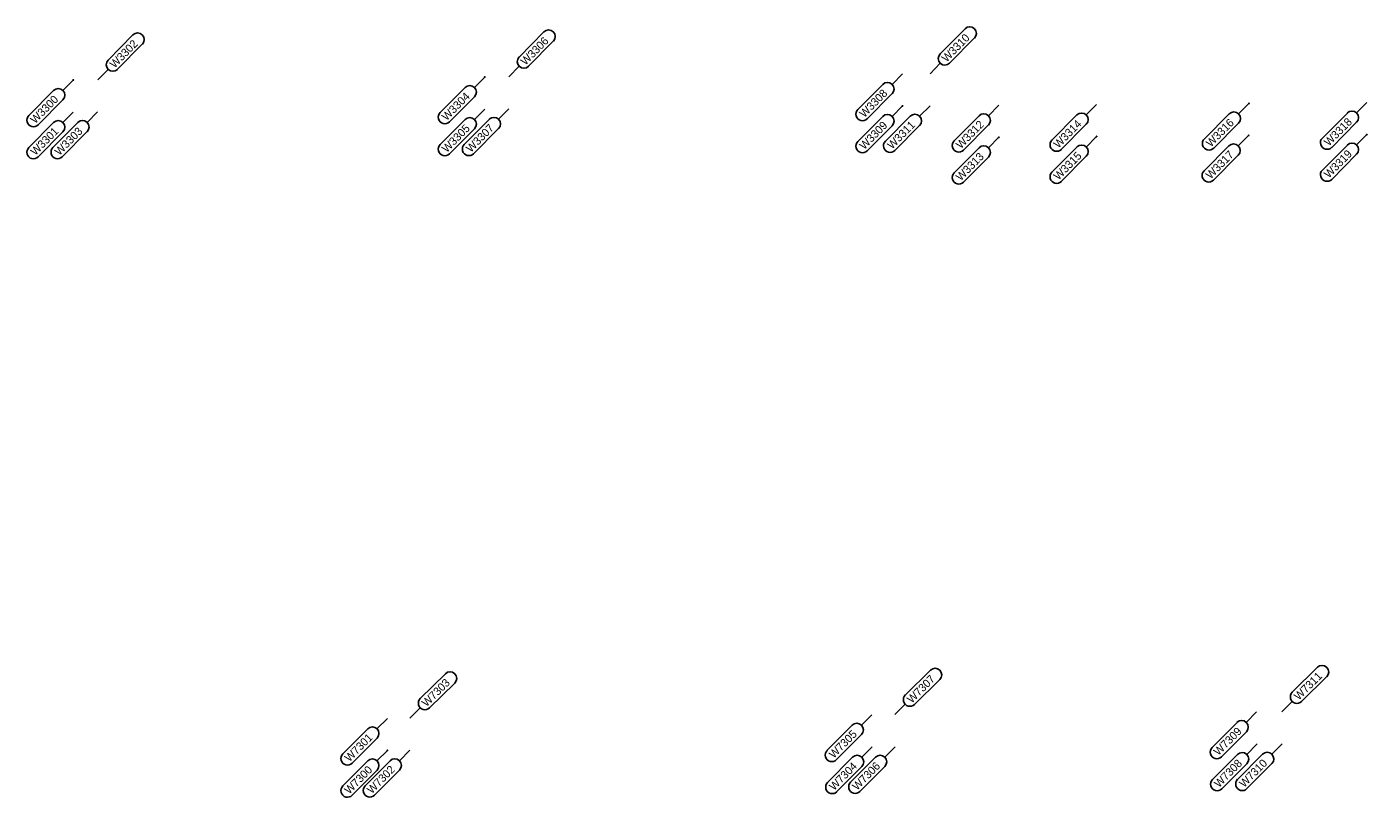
# Model space of a CAD drawing. Extents: x 12479652 to 12487250, y 9842710 to 9846560.
# Drawn here: x 12485622 to 12485831.3, y 9842757.5 to 9842877.8 of the extents above; entities that cross this region are included whole.
import ezdxf

# ---------------------------------------------------------------- set-up
doc = ezdxf.new("R2010")
doc.units = 0
doc.layers.add('_CIVIL_CONSTRUCTION', color=7, linetype='Continuous')
doc.layers.add('TextAlignmentLrg', color=7, linetype='Continuous')

msp = doc.modelspace()

# ---------------------------------------------------------------- linework, layer by layer
at = {"layer": '_CIVIL_CONSTRUCTION'}
for p, q in [((12485702.78, 9842876.99), (12485698.91, 9842873.07)), ((12485768.54, 9842877.48), (12485764.66, 9842873.55)), ((12485638.6, 9842876.52), (12485634.72, 9842872.59)), ((12485636.18, 9842871.15), (12485640.06, 9842875.08)), ((12485700.37, 9842871.62), (12485704.24, 9842875.55)), ((12485766.12, 9842872.11), (12485770, 9842876.04)), ((12485633.12, 9842869.5), (12485634.73, 9842871.14)), ((12485697.3, 9842869.98), (12485698.92, 9842871.62)), ((12485763.06, 9842870.46), (12485764.67, 9842872.1)), ((12485629.28, 9842869.48), (12485627.66, 9842867.84)), ((12485693.54, 9842869.95), (12485691.92, 9842868.32)), ((12485751.79, 9842864.88), (12485755.68, 9842868.8)), ((12485758.76, 9842870.43), (12485757.13, 9842868.8)), ((12485622.32, 9842863.93), (12485626.21, 9842867.84)), ((12485686.58, 9842864.4), (12485690.47, 9842868.31)), ((12485691.93, 9842866.87), (12485688.04, 9842862.96)), ((12485757.14, 9842867.35), (12485753.25, 9842863.44)), ((12485627.66, 9842866.39), (12485623.77, 9842862.48)), ((12485629.28, 9842864.48), (12485627.66, 9842862.84)), ((12485633.07, 9842864.5), (12485631.45, 9842862.87)), ((12485693.54, 9842864.95), (12485691.92, 9842863.32)), ((12485697.3, 9842864.98), (12485695.68, 9842863.35)), ((12485758.76, 9842865.43), (12485757.13, 9842863.8)), ((12485763.06, 9842865.46), (12485761.43, 9842863.83)), ((12485773.8, 9842865.54), (12485772.18, 9842863.91)), ((12485789.07, 9842865.66), (12485787.45, 9842864.02)), ((12485812.87, 9842865.83), (12485811.25, 9842864.2)), ((12485831.3, 9842865.97), (12485829.68, 9842864.34)), ((12485622.32, 9842858.93), (12485626.21, 9842862.84)), ((12485626.11, 9842858.95), (12485630, 9842862.87)), ((12485686.58, 9842859.4), (12485690.47, 9842863.31)), ((12485690.34, 9842859.43), (12485694.23, 9842863.34)), ((12485751.79, 9842859.88), (12485755.68, 9842863.8)), ((12485757.14, 9842862.35), (12485753.25, 9842858.44)), ((12485756.09, 9842859.92), (12485759.98, 9842863.83)), ((12485761.44, 9842862.38), (12485757.55, 9842858.47)), ((12485766.84, 9842859.99), (12485770.73, 9842863.91)), ((12485772.19, 9842862.46), (12485768.3, 9842858.55)), ((12485782.11, 9842860.11), (12485786, 9842864.02)), ((12485787.45, 9842862.57), (12485783.56, 9842858.66)), ((12485805.91, 9842860.28), (12485809.8, 9842864.2)), ((12485811.25, 9842862.75), (12485807.36, 9842858.84)), ((12485824.34, 9842860.42), (12485828.23, 9842864.33)), ((12485829.68, 9842862.89), (12485825.79, 9842858.97)), ((12485627.66, 9842861.39), (12485623.77, 9842857.48)), ((12485631.45, 9842861.42), (12485627.56, 9842857.51)), ((12485691.93, 9842861.87), (12485688.04, 9842857.96)), ((12485695.68, 9842861.9), (12485691.79, 9842857.98)), ((12485773.8, 9842860.54), (12485772.18, 9842858.91)), ((12485789.07, 9842860.66), (12485787.45, 9842859.02)), ((12485812.82, 9842860.83), (12485811.2, 9842859.2)), ((12485831.3, 9842860.97), (12485829.68, 9842859.34)), ((12485766.84, 9842854.99), (12485770.73, 9842858.91)), ((12485782.11, 9842855.11), (12485786, 9842859.02)), ((12485805.86, 9842855.28), (12485809.75, 9842859.2)), ((12485824.34, 9842855.42), (12485828.23, 9842859.33)), ((12485772.19, 9842857.46), (12485768.3, 9842853.55)), ((12485787.45, 9842857.57), (12485783.56, 9842853.66)), ((12485811.2, 9842857.75), (12485807.31, 9842853.84)), ((12485829.68, 9842857.89), (12485825.79, 9842853.97)), ((12485687.4, 9842776.81), (12485683.47, 9842772.93)), ((12485763.14, 9842777.36), (12485759.21, 9842773.49)), ((12485823.57, 9842777.81), (12485819.64, 9842773.93)), ((12485684.91, 9842771.47), (12485688.84, 9842775.35)), ((12485760.65, 9842772.03), (12485764.58, 9842775.91)), ((12485821.08, 9842772.47), (12485825.01, 9842776.35)), ((12485818, 9842770.87), (12485819.63, 9842772.48)), ((12485681.82, 9842769.86), (12485683.46, 9842771.48)), ((12485753.98, 9842770.39), (12485752.35, 9842768.76)), ((12485757.57, 9842770.42), (12485759.2, 9842772.04)), ((12485814.07, 9842770.84), (12485812.45, 9842769.21)), ((12485671.36, 9842764.29), (12485675.25, 9842768.2)), ((12485678.32, 9842769.84), (12485676.7, 9842768.2)), ((12485747.01, 9842764.85), (12485750.9, 9842768.76)), ((12485807.11, 9842765.29), (12485811, 9842769.2)), ((12485676.71, 9842766.75), (12485672.82, 9842762.84)), ((12485752.36, 9842767.31), (12485748.47, 9842763.4)), ((12485812.46, 9842767.76), (12485808.57, 9842763.84)), ((12485678.32, 9842764.84), (12485676.7, 9842763.2)), ((12485681.82, 9842764.86), (12485680.2, 9842763.23)), ((12485754.03, 9842765.39), (12485752.41, 9842763.76)), ((12485757.62, 9842765.42), (12485756, 9842763.79)), ((12485807.18, 9842760.29), (12485811.07, 9842764.2)), ((12485811.1, 9842760.32), (12485814.99, 9842764.23)), ((12485814.14, 9842765.84), (12485812.52, 9842764.21)), ((12485818.07, 9842765.87), (12485816.44, 9842764.24)), ((12485671.36, 9842759.29), (12485675.25, 9842763.2)), ((12485674.86, 9842759.31), (12485678.75, 9842763.23)), ((12485747.07, 9842759.85), (12485750.96, 9842763.76)), ((12485752.42, 9842762.31), (12485748.53, 9842758.4)), ((12485750.66, 9842759.87), (12485754.55, 9842763.79)), ((12485756.01, 9842762.34), (12485752.12, 9842758.43)), ((12485812.53, 9842762.76), (12485808.64, 9842758.84)), ((12485816.45, 9842762.79), (12485812.56, 9842758.87)), ((12485676.71, 9842761.75), (12485672.82, 9842757.84)), ((12485680.21, 9842761.78), (12485676.32, 9842757.87))]:
    msp.add_line(p, q, dxfattribs=at)
for centre, start, end in [((12485703.51, 9842876.27), 315.3788, 135.3788), ((12485769.27, 9842876.76), 315.3788, 135.3788), ((12485639.33, 9842875.8), 315.3788, 135.3788), ((12485699.64, 9842872.35), 135.3788, 315.3788), ((12485765.39, 9842872.83), 135.3788, 315.3788), ((12485635.45, 9842871.87), 135.3788, 315.3788), ((12485691.2, 9842867.59), 315.1702, 135.1702), ((12485756.41, 9842868.07), 315.1702, 135.1702), ((12485626.94, 9842867.12), 315.1702, 135.1702), ((12485687.31, 9842863.68), 135.1702, 315.1702), ((12485752.52, 9842864.16), 135.1702, 315.1702), ((12485810.52, 9842863.47), 315.1702, 135.1702), ((12485828.95, 9842863.61), 315.1702, 135.1702), ((12485623.05, 9842863.2), 135.1702, 315.1702), ((12485626.94, 9842862.12), 315.1702, 135.1702), ((12485630.72, 9842862.14), 315.1702, 135.1702), ((12485691.2, 9842862.59), 315.1702, 135.1702), ((12485694.96, 9842862.62), 315.1702, 135.1702), ((12485756.41, 9842863.07), 315.1702, 135.1702), ((12485760.71, 9842863.1), 315.1702, 135.1702), ((12485771.46, 9842863.18), 315.1702, 135.1702), ((12485786.73, 9842863.3), 315.1702, 135.1702), ((12485806.63, 9842859.56), 135.1702, 315.1702), ((12485825.06, 9842859.7), 135.1702, 315.1702), ((12485623.05, 9842858.2), 135.1702, 315.1702), ((12485626.83, 9842858.23), 135.1702, 315.1702), ((12485687.31, 9842858.68), 135.1702, 315.1702), ((12485691.07, 9842858.71), 135.1702, 315.1702), ((12485752.52, 9842859.16), 135.1702, 315.1702), ((12485756.82, 9842859.19), 135.1702, 315.1702), ((12485767.57, 9842859.27), 135.1702, 315.1702), ((12485771.46, 9842858.18), 315.1702, 135.1702), ((12485782.84, 9842859.38), 135.1702, 315.1702), ((12485786.73, 9842858.3), 315.1702, 135.1702), ((12485810.47, 9842858.47), 315.1702, 135.1702), ((12485828.95, 9842858.61), 315.1702, 135.1702), ((12485767.57, 9842854.27), 135.1702, 315.1702), ((12485782.84, 9842854.38), 135.1702, 315.1702), ((12485806.58, 9842854.56), 135.1702, 315.1702), ((12485825.06, 9842854.7), 135.1702, 315.1702), ((12485688.12, 9842776.08), 314.6453, 134.6453), ((12485763.86, 9842776.63), 314.6453, 134.6453), ((12485824.29, 9842777.08), 314.6453, 134.6453), ((12485684.19, 9842772.2), 134.6453, 314.6453), ((12485759.93, 9842772.76), 134.6453, 314.6453), ((12485820.36, 9842773.2), 134.6453, 314.6453), ((12485675.98, 9842767.48), 315.1702, 135.1702), ((12485751.63, 9842768.04), 315.1702, 135.1702), ((12485811.73, 9842768.48), 315.1702, 135.1702), ((12485672.09, 9842763.56), 135.1702, 315.1702), ((12485747.74, 9842764.12), 135.1702, 315.1702), ((12485751.69, 9842763.04), 315.1702, 135.1702), ((12485755.28, 9842763.06), 315.1702, 135.1702), ((12485807.84, 9842764.57), 135.1702, 315.1702), ((12485811.8, 9842763.48), 315.1702, 135.1702), ((12485815.72, 9842763.51), 315.1702, 135.1702), ((12485675.98, 9842762.48), 315.1702, 135.1702), ((12485679.48, 9842762.5), 315.1702, 135.1702), ((12485747.8, 9842759.12), 135.1702, 315.1702), ((12485751.39, 9842759.15), 135.1702, 315.1702), ((12485807.91, 9842759.57), 135.1702, 315.1702), ((12485811.83, 9842759.6), 135.1702, 315.1702), ((12485672.09, 9842758.56), 135.1702, 315.1702), ((12485675.59, 9842758.59), 135.1702, 315.1702)]:
    msp.add_arc(centre, 1.03, start, end, dxfattribs=at)
at = {"layer": 'TextAlignmentLrg'}
for centre in [(12485629.28, 9842869.48), (12485693.54, 9842869.95), (12485758.76, 9842865.43), (12485812.87, 9842865.83), (12485773.8, 9842860.54), (12485789.07, 9842860.66), (12485812.82, 9842860.83), (12485831.28, 9842860.95), (12485678.32, 9842764.84)]:
    msp.add_circle(centre, 0.05, dxfattribs=at)

# ---------------------------------------------------------------- texts
at = {"layer": '_CIVIL_CONSTRUCTION'}
for s, rotation, p in [('W3302', 45.3788, (12485635.73, 9842871.24)), ('W3306', 45.3788, (12485699.89, 9842871.69)), ('W3310', 45.3788, (12485765.64, 9842872.18)), ('W3300', 45.1702, (12485623.32, 9842862.58)), ('W3304', 45.1702, (12485687.57, 9842863.04)), ('W3308', 45.1702, (12485752.79, 9842863.53)), ('W3305', 45.1702, (12485687.59, 9842858.06)), ('W3307', 45.1702, (12485691.35, 9842858.09)), ('W3309', 45.1702, (12485752.79, 9842858.53)), ('W3311', 45.1702, (12485757.13, 9842858.6)), ('W3312', 45.1702, (12485767.86, 9842858.66)), ('W3314', 45.1702, (12485783.1, 9842858.75)), ('W3316', 45.1702, (12485806.9, 9842858.93)), ('W3318', 45.1702, (12485825.34, 9842859.07)), ('W3301', 45.1702, (12485623.35, 9842857.61)), ('W3303', 45.1702, (12485627.11, 9842857.61)), ('W3315', 45.1702, (12485783.12, 9842853.77)), ('W3317', 45.1702, (12485806.87, 9842853.94)), ('W3319', 45.1702, (12485825.34, 9842854.07)), ('W3313', 45.1702, (12485767.85, 9842853.65)), ('W7307', 44.6453, (12485760.19, 9842772.12)), ('W7311', 44.6453, (12485820.64, 9842772.59)), ('W7303', 44.6453, (12485684.44, 9842771.55)), ('W7309', 45.1702, (12485808.11, 9842763.94)), ('W7301', 45.1702, (12485672.4, 9842762.97)), ('W7305', 45.1702, (12485748.03, 9842763.51)), ('W7300', 45.1702, (12485672.36, 9842757.93)), ('W7302', 45.1702, (12485675.88, 9842757.98)), ('W7304', 45.1702, (12485748.06, 9842758.49)), ('W7306', 45.1702, (12485751.66, 9842758.52)), ('W7308', 45.1702, (12485808.18, 9842758.94)), ('W7310', 45.1702, (12485812.1, 9842758.97))]:
    msp.add_text(s, height=1.25, rotation=rotation, dxfattribs=at).set_placement(p)

doc.saveas('drawing.dxf')
